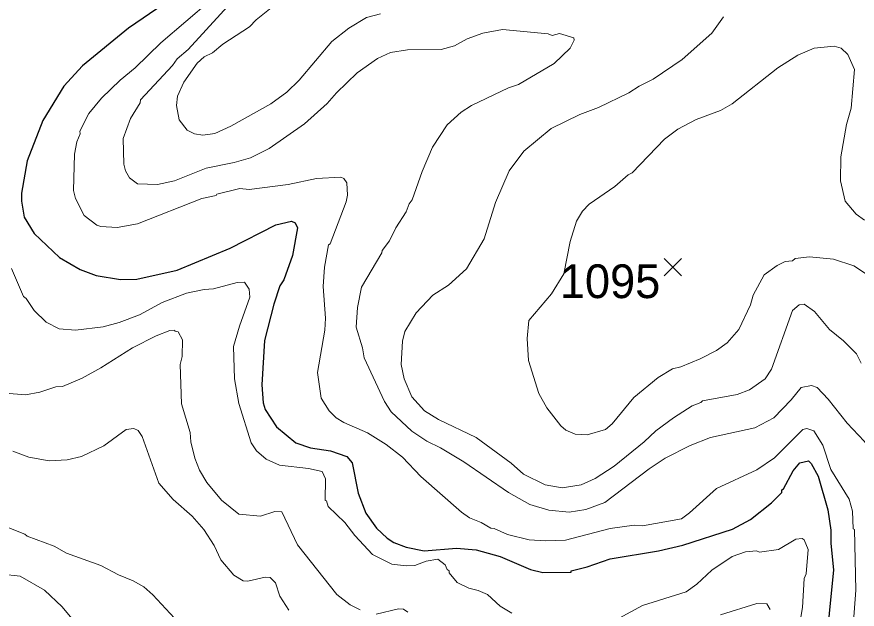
# Model space of a CAD drawing. Extents: x 265.7 to 292.1, y 7676.2 to 7704.2.
# Drawn here: x 288.41 to 290.402, y 7680.733 to 7682.139 of the extents above; entities that cross this region are included whole.
import ezdxf
from ezdxf.enums import TextEntityAlignment as Align

# ---------------------------------------------------------------- set-up
doc = ezdxf.new("R2010")
doc.units = 0
doc.header["$LTSCALE"] = 0.032
for name, color, linetype, lineweight in [('1', 7, 'Continuous', 25), ('2', 7, 'Continuous', 13), ('21', 7, 'Continuous', 25)]:
    doc.layers.add(name, color=color, linetype=linetype, lineweight=lineweight)
doc.layers.add('61', color=7, linetype='Continuous')

msp = doc.modelspace()

# ---------------------------------------------------------------- linework, layer by layer
at = {"layer": '1'}
msp.add_lwpolyline([(288.8614, 7682.24), (288.6754, 7682.1115), (288.5661, 7682.0221), (288.5222, 7681.9743), (288.4719, 7681.8929), (288.4352, 7681.7971), (288.4217, 7681.7205), (288.4217, 7681.7014), (288.4281, 7681.6631), (288.452, 7681.6248), (288.5118, 7681.5673), (288.5605, 7681.5394), (288.5988, 7681.525), (288.6563, 7681.5154), (288.6946, 7681.5162), (288.7903, 7681.5378), (288.9164, 7681.5896), (289.0241, 7681.6455), (289.0616, 7681.6535), (289.0704, 7681.6495), (289.076, 7681.6383), (289.064, 7681.5721), (289.0433, 7681.5147), (289.0337, 7681.5003), (289.0193, 7681.4572), (288.9978, 7681.371), (288.9914, 7681.2657), (288.9946, 7681.2226), (288.9994, 7681.2074), (289.0257, 7681.1659), (289.072, 7681.1284), (289.1063, 7681.1165), (289.1542, 7681.1093), (289.1925, 7681.0957), (289.2053, 7681.0806), (289.2196, 7681.0087), (289.238, 7680.9609), (289.2627, 7680.9258), (289.2883, 7680.9018), (289.3042, 7680.8914), (289.333, 7680.8803), (289.376, 7680.8715), (289.4526, 7680.8779), (289.4989, 7680.8739), (289.5564, 7680.8587), (289.6282, 7680.8276), (289.6569, 7680.8204), (289.724, 7680.8212), (289.7247, 7680.8244), (289.7623, 7680.834), (289.8165, 7680.8531), (289.9314, 7680.8715), (289.9889, 7680.885), (290.107, 7680.9233), (290.1493, 7680.9465), (290.1995, 7680.9856), (290.2235, 7681.0103), (290.2235, 7681.0167), (290.2274, 7681.0191), (290.2506, 7681.0614), (290.2666, 7681.0806), (290.2865, 7681.0853), (290.2929, 7681.0789), (290.3096, 7681.0486), (290.3328, 7680.9688), (290.34, 7680.921), (290.34, 7680.889), (290.3464, 7680.8268), (290.3256, 7680.6193)], dxfattribs=at)
at = {"layer": '2'}
for points in [[(288.9356, 7682.1921), (288.8167, 7682.0613), (288.7903, 7682.0389), (288.7792, 7682.023), (288.7034, 7681.9416), (288.7026, 7681.9344), (288.6802, 7681.8977), (288.6627, 7681.8498), (288.6643, 7681.7891), (288.6682, 7681.7732), (288.6778, 7681.7564), (288.6962, 7681.7421), (288.7441, 7681.7405), (288.784, 7681.7492), (288.859, 7681.7796), (288.926, 7681.7931), (288.9643, 7681.8043), (289.0082, 7681.8258), (289.092, 7681.8849), (289.1462, 7681.9328), (289.1678, 7681.9583), (289.2172, 7682.0054), (289.2651, 7682.0397), (289.2962, 7682.0541), (289.3361, 7682.0604), (289.4159, 7682.0612), (289.4479, 7682.07), (289.4782, 7682.086), (289.5149, 7682.0996), (289.5612, 7682.1083), (289.6697, 7682.098), (289.6793, 7682.094), (289.6968, 7682.0988), (289.7303, 7682.0884), (289.7311, 7682.0828), (289.7216, 7682.0644), (289.6841, 7682.0277), (289.5995, 7681.9783), (289.5755, 7681.9703), (289.4878, 7681.928), (289.4638, 7681.912), (289.4303, 7681.8825), (289.396, 7681.829), (289.3712, 7681.7716), (289.3473, 7681.7046), (289.3401, 7681.695), (289.3329, 7681.6758), (289.309, 7681.6383), (289.2938, 7681.6072), (289.2763, 7681.5841), (289.2755, 7681.5785), (289.2276, 7681.4971), (289.218, 7681.4492), (289.2148, 7681.4021), (289.23, 7681.3535), (289.234, 7681.3295), (289.2819, 7681.2258), (289.2978, 7681.2018), (289.3465, 7681.1556), (289.3824, 7681.1316), (289.4143, 7681.1165), (289.4702, 7681.0829), (289.5755, 7681.0103), (289.6266, 7680.9816), (289.6713, 7680.968)], [(289.5109, 7680.9393), (289.483, 7680.9505), (289.4646, 7680.9633), (289.3681, 7681.0478), (289.3242, 7681.0941), (289.2859, 7681.1244), (289.242, 7681.1516), (289.1853, 7681.1763), (289.167, 7681.1875), (289.151, 7681.2042), (289.1319, 7681.2338), (289.1231, 7681.2952), (289.1406, 7681.395), (289.1422, 7681.4237), (289.1366, 7681.4987), (289.1398, 7681.545), (289.1494, 7681.5976), (289.1534, 7681.6), (289.1909, 7681.6998), (289.1941, 7681.7157), (289.1925, 7681.7445), (289.1853, 7681.7548), (289.1781, 7681.758), (289.1207, 7681.7548), (289.0537, 7681.7405), (288.9611, 7681.7293), (288.9388, 7681.7309), (288.8845, 7681.7181), (288.8829, 7681.7149), (288.8494, 7681.7077), (288.6962, 7681.6471), (288.6483, 7681.6391), (288.61, 7681.6415), (288.6004, 7681.6447), (288.5701, 7681.6671), (288.5494, 7681.7078), (288.5446, 7681.7269), (288.547, 7681.8131), (288.5525, 7681.8418), (288.5605, 7681.861), (288.5597, 7681.8673), (288.5813, 7681.9088), (288.6116, 7681.9455), (288.6555, 7681.9886), (288.6914, 7682.0174), (288.752, 7682.0772), (288.8701, 7682.1777)], [(289.2723, 7682.1458), (289.2396, 7682.1371), (289.1973, 7682.1115), (289.1574, 7682.0796), (289.08, 7681.9886), (289.0505, 7681.9599), (289.0122, 7681.932), (288.918, 7681.8793), (288.8797, 7681.8618), (288.851, 7681.8578), (288.8318, 7681.861), (288.8143, 7681.8697), (288.7951, 7681.8945), (288.7887, 7681.928), (288.7911, 7681.9503), (288.8063, 7681.9839), (288.8382, 7682.0285), (288.8542, 7682.0437), (288.8741, 7682.0533), (288.8989, 7682.074), (288.9619, 7682.1147), (288.9779, 7682.1315), (289.0249, 7682.169)], [(290.4118, 7681.3168), (290.4006, 7681.3391), (290.3695, 7681.3702), (290.3368, 7681.3965), (290.3009, 7681.4396), (290.2769, 7681.4572), (290.265, 7681.4556), (290.249, 7681.442), (290.1995, 7681.3024), (290.1844, 7681.28), (290.1469, 7681.2537), (290.1181, 7681.2425), (290.0352, 7681.2274), (290.032, 7681.2234), (290.0112, 7681.2154), (289.9665, 7681.1875), (289.925, 7681.1564), (289.8971, 7681.13), (289.8261, 7681.0726), (289.7814, 7681.0438), (289.7479, 7681.0287), (289.7032, 7681.0215), (289.6625, 7681.0287), (289.6114, 7681.0534), (289.5819, 7681.0798), (289.4989, 7681.1404), (289.4096, 7681.1835), (289.3768, 7681.2042), (289.3465, 7681.237), (289.3282, 7681.28), (289.3218, 7681.3136), (289.3242, 7681.3694), (289.3298, 7681.3918), (289.3569, 7681.4365), (289.3968, 7681.4779), (289.4335, 7681.5019), (289.4766, 7681.541), (289.5181, 7681.612), (289.5452, 7681.6982), (289.5771, 7681.7732), (289.6122, 7681.8195), (289.6769, 7681.8737), (289.7447, 7681.9072), (289.7894, 7681.9232), (289.8612, 7681.9583), (289.8851, 7681.9743), (289.9187, 7681.991), (289.9873, 7682.0373), (290.0575, 7682.0995), (290.0854, 7682.1387)], [(290.4198, 7681.6559), (290.3998, 7681.6702), (290.3735, 7681.7014), (290.3623, 7681.7493), (290.3631, 7681.8067), (290.3767, 7681.8833), (290.3878, 7681.9216), (290.3958, 7682.0134), (290.3799, 7682.0493), (290.3639, 7682.0644), (290.348, 7682.0692), (290.3001, 7682.0644), (290.2618, 7682.0477), (290.2139, 7682.0174), (290.1062, 7681.932), (290.0782, 7681.916), (290.0208, 7681.8953), (289.9769, 7681.8721), (289.9458, 7681.8482), (289.8692, 7681.7684), (289.8596, 7681.7636), (289.8277, 7681.7357), (289.767, 7681.6942), (289.7513, 7681.6772)], [(289.7513, 7681.6772), (289.7367, 7681.6535), (289.7216, 7681.6056), (289.7072, 7681.529), (289.6777, 7681.4811), (289.6242, 7681.4181), (289.6202, 7681.3758), (289.6234, 7681.3231), (289.6473, 7681.2449), (289.6665, 7681.2114), (289.7, 7681.1683), (289.712, 7681.158), (289.7335, 7681.1484), (289.7623, 7681.1468), (289.8053, 7681.1596), (289.8213, 7681.1731), (289.8732, 7681.2354), (289.9306, 7681.2832), (289.9641, 7681.3032), (289.9841, 7681.308), (290.0304, 7681.3271), (290.0687, 7681.3471), (290.0942, 7681.3654), (290.1213, 7681.3966), (290.1493, 7681.4556), (290.1556, 7681.4779), (290.182, 7681.5266), (290.2123, 7681.549), (290.2315, 7681.5585), (290.249, 7681.5601), (290.2554, 7681.5649), (290.2889, 7681.5689), (290.3464, 7681.5633), (290.3942, 7681.5482), (290.4613, 7681.5035)], [(288.3977, 7681.5418), (288.4265, 7681.4748), (288.4328, 7681.47), (288.452, 7681.442), (288.4799, 7681.4141), (288.5111, 7681.3981)], [(288.8127, 7681.4827), (288.8542, 7681.4915), (288.8765, 7681.4931), (288.9324, 7681.5083), (288.9499, 7681.5091), (288.9611, 7681.4923), (288.9627, 7681.4732), (288.938, 7681.4045), (288.9244, 7681.3567), (288.9268, 7681.28), (288.9364, 7681.221), (288.9659, 7681.1284), (288.9786, 7681.1093), (289.0018, 7681.0893), (289.0329, 7681.075), (289.1015, 7681.067), (289.1343, 7681.0598), (289.1422, 7681.0423), (289.1414, 7680.9912), (289.1446, 7680.9904), (289.1486, 7680.9768), (289.1877, 7680.9393), (289.2117, 7680.9082), (289.2531, 7680.8635), (289.2994, 7680.8404), (289.333, 7680.8364), (289.3537, 7680.8372), (289.3808, 7680.8476), (289.408, 7680.8523), (289.4255, 7680.8388), (289.4303, 7680.8276), (289.4351, 7680.8244), (289.4351, 7680.8196), (289.4542, 7680.7965), (289.4814, 7680.7829), (289.5037, 7680.7781), (289.5261, 7680.7686), (289.5564, 7680.7406), (289.5835, 7680.7239)], [(288.5111, 7681.3981), (288.5494, 7681.3949), (288.6148, 7681.4029), (288.6531, 7681.4133), (288.701, 7681.4317), (288.7552, 7681.4612), (288.8127, 7681.4827)], [(289.2244, 7680.7318), (289.2005, 7680.7438), (289.1686, 7680.7686), (289.076, 7680.8859), (289.0385, 7680.964), (289.0217, 7680.9648), (288.9882, 7680.9537), (288.9364, 7680.9585), (288.8957, 7680.992), (288.8606, 7681.0343), (288.8438, 7681.063), (288.8326, 7681.0917), (288.823, 7681.13), (288.8215, 7681.1524), (288.8007, 7681.2202), (288.7975, 7681.3136), (288.8023, 7681.3327), (288.8031, 7681.3726), (288.7927, 7681.391), (288.7848, 7681.3926), (288.7848, 7681.3949), (288.7728, 7681.3942), (288.7409, 7681.3822), (288.685, 7681.3535)], [(288.685, 7681.3535), (288.61, 7681.3056), (288.5653, 7681.2816), (288.519, 7681.2617), (288.5031, 7681.2609), (288.4648, 7681.2481), (288.4313, 7681.2417)], [(290.0064, 7681.122), (290.0543, 7681.1404), (290.1596, 7681.1635), (290.2043, 7681.1875), (290.2458, 7681.2298), (290.2698, 7681.2593), (290.2937, 7681.2641), (290.3073, 7681.2593), (290.3336, 7681.2314), (290.3783, 7681.1747), (290.419, 7681.1316), (290.4469, 7681.0941), (290.4692, 7681.0151), (290.474, 7680.9672), (290.4708, 7680.8938), (290.4724, 7680.8204), (290.4613, 7680.664)], [(288.4313, 7681.2417), (288.3435, 7681.2489)], [(288.4009, 7681.1085), (288.4392, 7681.0941), (288.4871, 7681.0853), (288.5302, 7681.0877), (288.5637, 7681.0957), (288.6164, 7681.1212), (288.6698, 7681.1596), (288.6882, 7681.1619), (288.6978, 7681.1572), (288.7073, 7681.1428), (288.7472, 7681.0327), (288.7808, 7680.9936), (288.8262, 7680.9537), (288.8534, 7680.9226), (288.8781, 7680.8843), (288.8941, 7680.8507), (288.9252, 7680.814), (288.9467, 7680.8005), (288.9579, 7680.7997), (288.9994, 7680.8092), (289.0106, 7680.8084), (289.0233, 7680.7957), (289.0337, 7680.7646), (289.0553, 7680.7311)], [(290.3871, 7680.6193), (290.399, 7680.7789), (290.3958, 7680.9226), (290.3926, 7680.9242), (290.391, 7680.9657), (290.3831, 7680.9944), (290.34, 7681.0646), (290.3208, 7681.1221), (290.2993, 7681.1564), (290.2825, 7681.1619), (290.2737, 7681.1596), (290.2059, 7681.0925), (290.1644, 7681.0638), (290.0687, 7681.0199), (290.0048, 7680.9617), (289.9857, 7680.9481), (289.8931, 7680.9313), (289.874, 7680.9329), (289.8165, 7680.925), (289.7112, 7680.897)], [(289.6713, 7680.968), (289.7192, 7680.9632), (289.7591, 7680.9696), (289.8038, 7680.9864), (289.9091, 7681.0662), (289.9474, 7681.0917), (290.0064, 7681.122)], [(287.5335, 7680.7039), (287.5686, 7680.7486), (287.6117, 7680.7901), (287.6764, 7680.8348), (287.7171, 7680.8547), (287.7713, 7680.8906), (287.82, 7680.9138), (287.8727, 7680.9321), (287.9062, 7680.9393), (287.9397, 7680.9401), (287.9501, 7680.9433), (288.0562, 7680.9313), (288.0945, 7680.9154), (288.128, 7680.897), (288.2078, 7680.8428), (288.2637, 7680.8212), (288.2972, 7680.8164), (288.3754, 7680.8164), (288.4185, 7680.8116), (288.4759, 7680.7789), (288.5182, 7680.739), (288.5829, 7680.6608)], [(288.7943, 7680.7007), (288.7329, 7680.7678), (288.7113, 7680.7861), (288.6866, 7680.8005), (288.6515, 7680.8148), (288.61, 7680.8372), (288.5286, 7680.8667), (288.4991, 7680.8827), (288.4352, 7680.9066), (288.4297, 7680.9114), (288.3451, 7680.9449)], [(289.7112, 7680.897), (289.6633, 7680.8954), (289.625, 7680.8978), (289.5731, 7680.9106), (289.542, 7680.925), (289.534, 7680.9257), (289.5109, 7680.9393)], [(289.8101, 7680.6975), (289.8931, 7680.7422), (289.9969, 7680.7749), (290.0224, 7680.7925), (290.0575, 7680.826), (290.1062, 7680.8587), (290.1373, 7680.8691), (290.1636, 7680.8715), (290.1708, 7680.8683), (290.2155, 7680.8747), (290.257, 7680.8994), (290.2714, 7680.901), (290.2769, 7680.8978), (290.2857, 7680.8747), (290.2809, 7680.8172), (290.2769, 7680.8061), (290.2729, 7680.7374), (290.261, 7680.6672)], [(289.3369, 7680.7263), (289.3266, 7680.7334), (289.3154, 7680.7342), (289.2619, 7680.7215)], [(290.1963, 7680.7326), (290.1884, 7680.7462), (290.1644, 7680.747), (290.0782, 7680.7199)]]:
    msp.add_lwpolyline(points, dxfattribs=at)
at = {"layer": '21'}
for p, q in [((289.9444, 7681.5651), (289.9856, 7681.5239)), ((289.9856, 7681.5651), (289.9444, 7681.5239))]:
    msp.add_line(p, q, dxfattribs=at)

# ---------------------------------------------------------------- texts
at = {"layer": '61'}
msp.add_text('1095', height=0.08, dxfattribs=at).set_placement((289.8165, 7681.4713), align=Align.CENTER)

doc.saveas('drawing.dxf')
